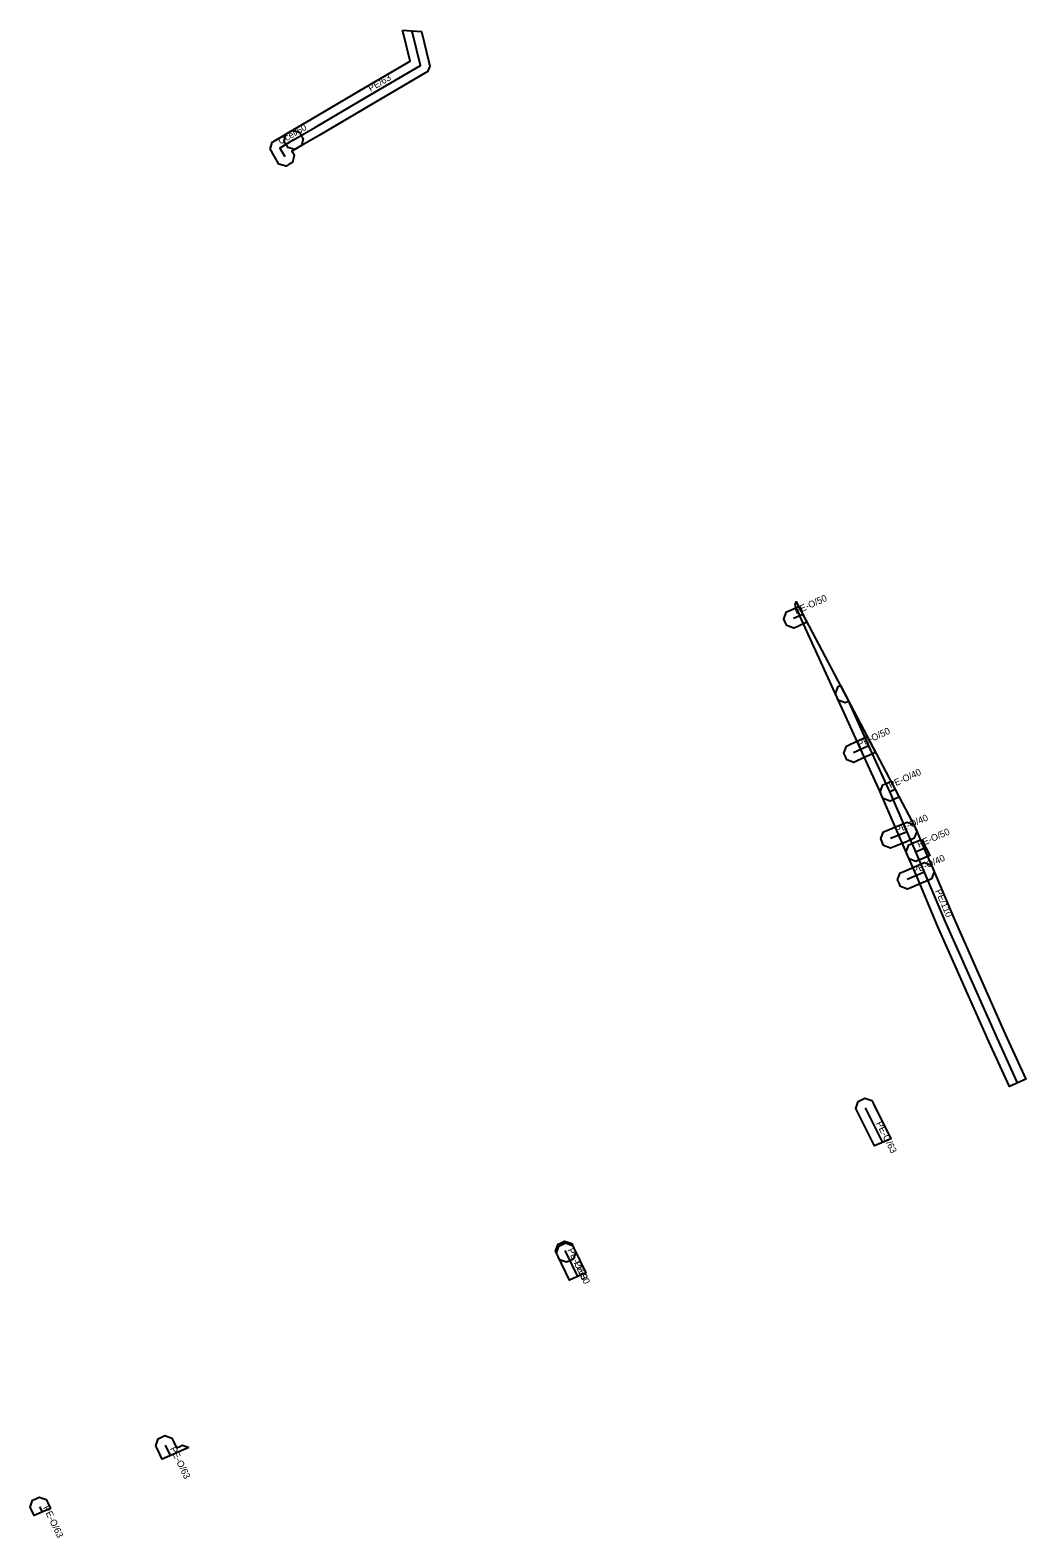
# Model space of a CAD drawing. Extents: x -492390 to -492156, y -1126301 to -1126086.
# Drawn here: x -492267.1 to -492155.9, y -1126259 to -1126090.6 of the extents above; entities that cross this region are included whole.
import ezdxf

# ---------------------------------------------------------------- set-up
doc = ezdxf.new("R2010")
doc.units = 0
for name, color, linetype in [('1', 7, 'Continuous'), ('14', 7, 'Continuous'), ('20', 7, 'Continuous'), ('24', 7, 'Continuous'), ('30', 7, 'Continuous')]:
    doc.layers.add(name, color=color, linetype=linetype)

msp = doc.modelspace()

# ---------------------------------------------------------------- linework, layer by layer
at = {"layer": '1'}
for points in [[(-492225.51, -1126090.56), (-492223.41, -1126090.72), (-492222.55, -1126094.27), (-492222.47, -1126094.6), (-492222.73, -1126095.21), (-492223.01, -1126095.37), (-492229.18, -1126099), (-492234.73, -1126102.26), (-492237.17, -1126103.69), (-492237.53, -1126103.9), (-492238.33, -1126103.69), (-492238.54, -1126103.34), (-492238.75, -1126102.98), (-492238.54, -1126102.18), (-492238.19, -1126101.97), (-492235.75, -1126100.54), (-492230.2, -1126097.27), (-492224.67, -1126094.02), (-492225.37, -1126091.11)], [(-492237.17, -1126103.69), (-492237.86, -1126104.1), (-492237.81, -1126104.18), (-492237.6, -1126104.54), (-492237.8, -1126105.34), (-492238.16, -1126105.55), (-492238.52, -1126105.76), (-492239.32, -1126105.55), (-492239.53, -1126105.2), (-492240.09, -1126104.25), (-492240.3, -1126103.89), (-492240.2, -1126103.49), (-492240.09, -1126103.08), (-492239.73, -1126102.88), (-492239.05, -1126102.48), (-492238.19, -1126101.97), (-492237.83, -1126101.76), (-492237.03, -1126101.96), (-492236.82, -1126102.32), (-492236.61, -1126102.68), (-492236.81, -1126103.48)], [(-492182.27, -1126155.39), (-492181.28, -1126154.94), (-492180.35, -1126156.71), (-492181.45, -1126157.21), (-492181.83, -1126157.38), (-492182.6, -1126157.09), (-492182.77, -1126156.71), (-492182.94, -1126156.33), (-492182.65, -1126155.56)], [(-492181.67, -1126154.79), (-492181.54, -1126154.44), (-492168.31, -1126179.56), (-492168.24, -1126179.72), (-492167.28, -1126181.95), (-492166.29, -1126184.24), (-492163.95, -1126189.77), (-492158.21, -1126202.74), (-492155.9, -1126207.78), (-492157.73, -1126208.59), (-492160.03, -1126203.56), (-492165.79, -1126190.57), (-492168.13, -1126185.02), (-492169.12, -1126182.75), (-492170.08, -1126180.52), (-492172.02, -1126176.03), (-492172.14, -1126175.74), (-492174.33, -1126170.92), (-492177, -1126165.06), (-492181.13, -1126155.98), (-492181.27, -1126155.67), (-492181.27, -1126155.66), (-492181.5, -1126155.17)], [(-492176.62, -1126163.79), (-492175.68, -1126165.56), (-492175.7, -1126165.57), (-492176.08, -1126165.73), (-492176.85, -1126165.43), (-492177.01, -1126165.04), (-492177.17, -1126164.66), (-492176.86, -1126163.89)], [(-492173.84, -1126169.6), (-492173.61, -1126169.5), (-492172.68, -1126171.27), (-492173, -1126171.42), (-492173.27, -1126171.54), (-492174.73, -1126172.21), (-492175.11, -1126172.38), (-492175.89, -1126172.09), (-492176.06, -1126171.72), (-492176.23, -1126171.34), (-492175.94, -1126170.56), (-492175.57, -1126170.39), (-492174.1, -1126169.72)], [(-492170.99, -1126174.48), (-492170.05, -1126176.26), (-492170.42, -1126176.42), (-492170.69, -1126176.54), (-492171.07, -1126176.71), (-492171.85, -1126176.42), (-492172.01, -1126176.04), (-492172.18, -1126175.66), (-492171.89, -1126174.88), (-492171.51, -1126174.72), (-492171.24, -1126174.6)], [(-492168.43, -1126179.34), (-492168.3, -1126179.59), (-492168.23, -1126179.74), (-492168.08, -1126180.12), (-492168.4, -1126180.89), (-492168.78, -1126181.04), (-492169.24, -1126181.23), (-492170.65, -1126181.81), (-492171.03, -1126181.97), (-492171.8, -1126181.65), (-492171.96, -1126181.27), (-492172.11, -1126180.89), (-492171.79, -1126180.12), (-492171.41, -1126179.97), (-492170, -1126179.38), (-492169.54, -1126179.2), (-492169.16, -1126179.04)], [(-492167.56, -1126180.98), (-492166.63, -1126182.76), (-492167.57, -1126183.17), (-492167.8, -1126183.27), (-492168.18, -1126183.43), (-492168.95, -1126183.13), (-492169.12, -1126182.75), (-492169.28, -1126182.37), (-492168.98, -1126181.6), (-492168.6, -1126181.43), (-492168.37, -1126181.33)], [(-492166.43, -1126185.38), (-492166.81, -1126185.55), (-492167.28, -1126185.75), (-492168.74, -1126186.39), (-492169.12, -1126186.55), (-492169.89, -1126186.25), (-492170.06, -1126185.87), (-492170.22, -1126185.49), (-492169.92, -1126184.72), (-492169.54, -1126184.55), (-492168.08, -1126183.92), (-492167.61, -1126183.71), (-492167.23, -1126183.55), (-492166.46, -1126183.85), (-492166.29, -1126184.23), (-492166.13, -1126184.61)], [(-492172.92, -1126210.52), (-492170.98, -1126214.41), (-492172.81, -1126215.22), (-492174.71, -1126211.41), (-492174.89, -1126211.03), (-492174.63, -1126210.25), (-492174.26, -1126210.06), (-492173.88, -1126209.88), (-492173.1, -1126210.14)], [(-492207.98, -1126227.94), (-492208.15, -1126227.57), (-492208.25, -1126227.36), (-492208.43, -1126226.99), (-492208.15, -1126226.21), (-492207.78, -1126226.03), (-492207.41, -1126225.85), (-492206.62, -1126226.13), (-492206.45, -1126226.5), (-492206.35, -1126226.71), (-492206.17, -1126227.08), (-492206.45, -1126227.86), (-492206.82, -1126228.04), (-492207.19, -1126228.22)], [(-492206.35, -1126226.7), (-492205.04, -1126229.4), (-492206.87, -1126230.21), (-492208.15, -1126227.58), (-492208.33, -1126227.21), (-492208.06, -1126226.42), (-492207.69, -1126226.24), (-492207.32, -1126226.06), (-492206.53, -1126226.33)], [(-492249.37, -1126248.91), (-492252.35, -1126250.22), (-492252.89, -1126249.1), (-492253.07, -1126248.73), (-492252.8, -1126247.95), (-492252.42, -1126247.77), (-492252.05, -1126247.59), (-492251.27, -1126247.86), (-492251.09, -1126248.24), (-492250.74, -1126248.96), (-492250.47, -1126248.83), (-492250.1, -1126248.65)], [(-492265.12, -1126255.1), (-492264.83, -1126255.71), (-492266.66, -1126256.51), (-492266.92, -1126255.96), (-492267.1, -1126255.59), (-492266.83, -1126254.81), (-492266.45, -1126254.63), (-492266.08, -1126254.45), (-492265.3, -1126254.73)]]:
    msp.add_lwpolyline(points, close=True, dxfattribs=at)
at = {"layer": '14'}
for points in [[(-492180.81, -1126155.83), (-492181.86, -1126156.3)], [(-492156.82, -1126208.18), (-492159.12, -1126203.15), (-492164.87, -1126190.17), (-492167.21, -1126184.63), (-492168.2, -1126182.35), (-492169.16, -1126180.12), (-492171.1, -1126175.63), (-492171.23, -1126175.33), (-492173.42, -1126170.51), (-492175.6, -1126165.72)], [(-492173.42, -1126170.51), (-492173.68, -1126170.63), (-492175.15, -1126171.3)], [(-492171.1, -1126175.63), (-492170.83, -1126175.51), (-492170.52, -1126175.37)], [(-492169.16, -1126180.12), (-492169.62, -1126180.31), (-492171.03, -1126180.89)], [(-492168.2, -1126182.35), (-492167.97, -1126182.25), (-492167.1, -1126181.87)], [(-492167.21, -1126184.63), (-492167.68, -1126184.83), (-492169.14, -1126185.47)], [(-492171.89, -1126214.82), (-492173.81, -1126210.96)], [(-492207.25, -1126227.14), (-492207.35, -1126226.93)], [(-492205.95, -1126229.8), (-492207.25, -1126227.14)], [(-492251.44, -1126249.82), (-492251.99, -1126248.67)], [(-492265.74, -1126256.11), (-492266.02, -1126255.53)]]:
    msp.add_lwpolyline(points, dxfattribs=at)
at = {"layer": '24'}
for points in [[(-492237.68, -1126102.83), (-492235.24, -1126101.4), (-492229.69, -1126098.14), (-492223.52, -1126094.51), (-492224.4, -1126090.87), (-492224.46, -1126090.64)], [(-492237.68, -1126102.83), (-492238.54, -1126103.34), (-492239.23, -1126103.74), (-492238.67, -1126104.69)]]:
    msp.add_lwpolyline(points, dxfattribs=at)

# ---------------------------------------------------------------- texts
at = {"layer": '20'}
for s, rotation, p in [('PE-O/50', 24.3022, (-492181.54, -1126155.86)), ('PE-O/50', 24.5293, (-492174.48, -1126170.71)), ('PE-O/40', 24.4129, (-492171.01, -1126175.3)), ('PE-O/40', 22.3863, (-492170.3, -1126180.3)), ('PE-O/50', 23.4133, (-492167.85, -1126181.91)), ('PE-O/40', 23.5345, (-492168.38, -1126184.85)), ('PE/110', 292.8984, (-492166.04, -1126186.72)), ('PE-O/63', 296.4378, (-492172.65, -1126212.69)), ('PE-O/63', 295.4633, (-492207.1, -1126226.83)), ('PE/90', 295.9473, (-492206.4, -1126228.27)), ('PE-O/63', 295.71, (-492251.51, -1126249.04)), ('PE-O/63', 295.5316, (-492265.68, -1126255.62))]:
    msp.add_text(s, height=0.75, rotation=rotation, dxfattribs=at).set_placement(p)
at = {"layer": '30'}
for s, rotation, p in [('PE/63', 30.4501, (-492229.08, -1126097.46)), ('Ocel/50', 30.1013, (-492239.13, -1126103.37))]:
    msp.add_text(s, height=0.75, rotation=rotation, dxfattribs=at).set_placement(p)

doc.saveas('drawing.dxf')
